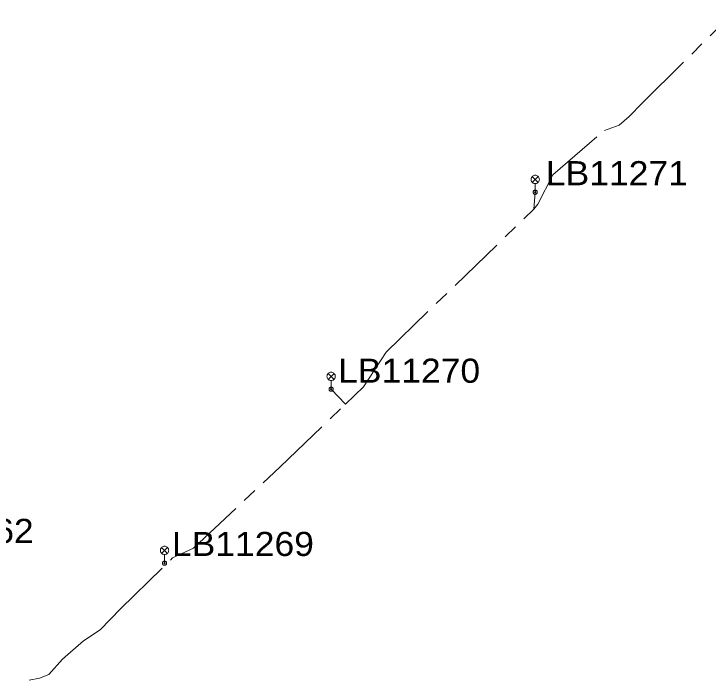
# Model space of a CAD drawing. Extents: x -688049 to -687261, y -973611 to -973038.
# Drawn here: x -687682.8 to -687620.3, y -973588.2 to -973528.3 of the extents above; entities that cross this region are included whole.
import ezdxf

# ---------------------------------------------------------------- set-up
doc = ezdxf.new("R2010")
doc.units = 0
doc.header["$LTSCALE"] = 0.87
doc.linetypes.add('LONG_DASH_SHORT_DASH', pattern=[9.9, 6, -1.2, 1.5, -1.2])
doc.layers.add('1', color=7, linetype='Continuous', lineweight=13)

msp = doc.modelspace()

# ---------------------------------------------------------------- linework, layer by layer
at = {"layer": '1'}
for p, q in [((-687636.154, -973542.962), (-687635.624, -973543.492)), ((-687636.154, -973543.492), (-687635.624, -973542.962)), ((-687635.889, -973544.377), (-687635.889, -973543.602)), ((-687654.505, -973560.675), (-687653.975, -973561.205)), ((-687654.505, -973561.205), (-687653.975, -973560.675)), ((-687654.24, -973562.09), (-687654.24, -973561.315)), ((-687669.484, -973576.322), (-687668.954, -973576.852)), ((-687669.484, -973576.852), (-687668.954, -973576.322)), ((-687669.219, -973577.737), (-687669.219, -973576.962))]:
    msp.add_line(p, q, dxfattribs=at)
at = {"layer": '1', "linetype": 'LONG_DASH_SHORT_DASH'}
msp.add_line((-687652.949, -973563.435), (-687654.24, -973562.09), dxfattribs=at)
msp.add_line((-687652.949, -973563.435), (-687654.24, -973562.09), dxfattribs=at)
msp.add_line((-687652.949, -973563.435), (-687654.24, -973562.09), dxfattribs=at)
msp.add_line((-687652.949, -973563.435), (-687654.24, -973562.09), dxfattribs=at)
msp.add_line((-687652.949, -973563.435), (-687654.24, -973562.09), dxfattribs=at)
for points in [[(-687636.02, -973545.9), (-687635.64, -973545.44), (-687634.29, -973542.81), (-687629.65, -973538.82), (-687628.33, -973538.35), (-687627.45, -973537.56), (-687626.27, -973536.36), (-687618.23, -973528.4), (-687617.66, -973528.34)], [(-687636.02, -973545.9), (-687635.64, -973545.44), (-687634.29, -973542.81), (-687629.65, -973538.82), (-687628.33, -973538.35), (-687627.45, -973537.56), (-687626.27, -973536.36), (-687618.23, -973528.4), (-687617.66, -973528.34)], [(-687636.02, -973545.9), (-687635.64, -973545.44), (-687634.29, -973542.81), (-687629.65, -973538.82), (-687628.33, -973538.35), (-687627.45, -973537.56), (-687626.27, -973536.36), (-687618.23, -973528.4), (-687617.66, -973528.34)], [(-687636.02, -973545.9), (-687635.64, -973545.44), (-687634.29, -973542.81), (-687629.65, -973538.82), (-687628.33, -973538.35), (-687627.45, -973537.56), (-687626.27, -973536.36), (-687618.23, -973528.4), (-687617.66, -973528.34)], [(-687636.02, -973545.9), (-687635.64, -973545.44), (-687634.29, -973542.81), (-687629.65, -973538.82), (-687628.33, -973538.35), (-687627.45, -973537.56), (-687626.27, -973536.36), (-687618.23, -973528.4), (-687617.66, -973528.34)], [(-687636.02, -973545.9), (-687635.64, -973545.44), (-687634.29, -973542.81), (-687629.65, -973538.82), (-687628.33, -973538.35), (-687627.45, -973537.56), (-687626.27, -973536.36), (-687618.23, -973528.4), (-687617.66, -973528.34)], [(-687636.02, -973545.9), (-687635.64, -973545.44), (-687634.29, -973542.81), (-687629.65, -973538.82), (-687628.33, -973538.35), (-687627.45, -973537.56), (-687626.27, -973536.36), (-687618.23, -973528.4), (-687617.66, -973528.34)], [(-687636.02, -973545.9), (-687635.64, -973545.44), (-687634.29, -973542.81), (-687629.65, -973538.82), (-687628.33, -973538.35), (-687627.45, -973537.56), (-687626.27, -973536.36), (-687618.23, -973528.4), (-687617.66, -973528.34)], [(-687652.949, -973563.435), (-687651.34, -973561.89), (-687649.28, -973558.75), (-687636.02, -973545.9), (-687635.88, -973544.37)], [(-687652.949, -973563.435), (-687651.34, -973561.89), (-687649.28, -973558.75), (-687636.02, -973545.9), (-687635.88, -973544.37)], [(-687652.949, -973563.435), (-687651.34, -973561.89), (-687649.28, -973558.75), (-687636.02, -973545.9), (-687635.88, -973544.37)], [(-687652.949, -973563.435), (-687651.34, -973561.89), (-687649.28, -973558.75), (-687636.02, -973545.9), (-687635.88, -973544.37)], [(-687652.949, -973563.435), (-687651.34, -973561.89), (-687649.28, -973558.75), (-687636.02, -973545.9), (-687635.88, -973544.37)], [(-687652.949, -973563.435), (-687651.34, -973561.89), (-687649.28, -973558.75), (-687636.02, -973545.9), (-687635.88, -973544.37)], [(-687652.949, -973563.435), (-687651.34, -973561.89), (-687649.28, -973558.75), (-687636.02, -973545.9), (-687635.88, -973544.37)], [(-687652.949, -973563.435), (-687651.34, -973561.89), (-687649.28, -973558.75), (-687636.02, -973545.9), (-687635.88, -973544.37)], [(-687681.395, -973588.25), (-687680.46, -973588.06), (-687679.62, -973587.76), (-687678.4, -973586.38), (-687676.51, -973584.72), (-687675, -973583.74), (-687673.17, -973581.85), (-687668.49, -973577.26), (-687666.63, -973576.38), (-687658.85, -973569.1), (-687652.949, -973563.435), (-687654.24, -973562.09)], [(-687681.395, -973588.25), (-687680.46, -973588.06), (-687679.62, -973587.76), (-687678.4, -973586.38), (-687676.51, -973584.72), (-687675, -973583.74), (-687673.17, -973581.85), (-687668.49, -973577.26), (-687666.63, -973576.38), (-687658.85, -973569.1), (-687652.949, -973563.435), (-687654.24, -973562.09)], [(-687681.395, -973588.25), (-687680.46, -973588.06), (-687679.62, -973587.76), (-687678.4, -973586.38), (-687676.51, -973584.72), (-687675, -973583.74), (-687673.17, -973581.85), (-687668.49, -973577.26), (-687666.63, -973576.38), (-687658.85, -973569.1), (-687652.949, -973563.435), (-687654.24, -973562.09)], [(-687681.395, -973588.25), (-687680.46, -973588.06), (-687679.62, -973587.76), (-687678.4, -973586.38), (-687676.51, -973584.72), (-687675, -973583.74), (-687673.17, -973581.85), (-687668.49, -973577.26), (-687666.63, -973576.38), (-687658.85, -973569.1), (-687652.949, -973563.435)], [(-687681.395, -973588.25), (-687680.46, -973588.06), (-687679.62, -973587.76), (-687678.4, -973586.38), (-687676.51, -973584.72), (-687675, -973583.74), (-687673.17, -973581.85), (-687668.49, -973577.26), (-687666.63, -973576.38), (-687658.85, -973569.1), (-687652.949, -973563.435)], [(-687681.395, -973588.25), (-687680.46, -973588.06), (-687679.62, -973587.76), (-687678.4, -973586.38), (-687676.51, -973584.72), (-687675, -973583.74), (-687673.17, -973581.85), (-687668.49, -973577.26), (-687666.63, -973576.38), (-687658.85, -973569.1), (-687652.949, -973563.435)], [(-687681.395, -973588.25), (-687680.46, -973588.06), (-687679.62, -973587.76), (-687678.4, -973586.38), (-687676.51, -973584.72), (-687675, -973583.74), (-687673.17, -973581.85), (-687668.49, -973577.26), (-687666.63, -973576.38), (-687658.85, -973569.1), (-687652.949, -973563.435)], [(-687681.395, -973588.25), (-687680.46, -973588.06), (-687679.62, -973587.76), (-687678.4, -973586.38), (-687676.51, -973584.72), (-687675, -973583.74), (-687673.17, -973581.85), (-687668.49, -973577.26), (-687666.63, -973576.38), (-687658.85, -973569.1), (-687652.949, -973563.435)]]:
    msp.add_lwpolyline(points, dxfattribs=at)
at = {"layer": '1'}
for points in [[(-687635.514, -973543.227), (-687635.52, -973543.162), (-687635.537, -973543.099), (-687635.564, -973543.04), (-687635.602, -973542.986), (-687635.648, -973542.94), (-687635.702, -973542.902), (-687635.761, -973542.875), (-687635.824, -973542.858), (-687635.889, -973542.852), (-687635.954, -973542.858), (-687636.017, -973542.875), (-687636.076, -973542.902), (-687636.13, -973542.94), (-687636.176, -973542.986), (-687636.214, -973543.04), (-687636.241, -973543.099), (-687636.258, -973543.162), (-687636.264, -973543.227), (-687636.258, -973543.292), (-687636.241, -973543.355), (-687636.214, -973543.414), (-687636.176, -973543.468), (-687636.13, -973543.514), (-687636.076, -973543.552), (-687636.017, -973543.579), (-687635.954, -973543.596), (-687635.889, -973543.602), (-687635.824, -973543.596), (-687635.761, -973543.579), (-687635.702, -973543.552), (-687635.648, -973543.514), (-687635.602, -973543.468), (-687635.564, -973543.414), (-687635.537, -973543.355), (-687635.52, -973543.292)], [(-687635.699, -973544.377), (-687635.702, -973544.344), (-687635.71, -973544.312), (-687635.724, -973544.282), (-687635.743, -973544.255), (-687635.767, -973544.231), (-687635.794, -973544.212), (-687635.824, -973544.198), (-687635.856, -973544.19), (-687635.889, -973544.187), (-687635.922, -973544.19), (-687635.954, -973544.198), (-687635.984, -973544.212), (-687636.011, -973544.231), (-687636.035, -973544.255), (-687636.054, -973544.282), (-687636.068, -973544.312), (-687636.076, -973544.344), (-687636.079, -973544.377), (-687636.076, -973544.41), (-687636.068, -973544.442), (-687636.054, -973544.472), (-687636.035, -973544.499), (-687636.011, -973544.523), (-687635.984, -973544.542), (-687635.954, -973544.556), (-687635.922, -973544.564), (-687635.889, -973544.567), (-687635.856, -973544.564), (-687635.824, -973544.556), (-687635.794, -973544.542), (-687635.767, -973544.523), (-687635.743, -973544.499), (-687635.724, -973544.472), (-687635.71, -973544.442), (-687635.702, -973544.41)], [(-687635.839, -973544.377), (-687635.84, -973544.368), (-687635.842, -973544.36), (-687635.846, -973544.352), (-687635.851, -973544.345), (-687635.857, -973544.339), (-687635.864, -973544.334), (-687635.872, -973544.33), (-687635.88, -973544.328), (-687635.889, -973544.327), (-687635.898, -973544.328), (-687635.906, -973544.33), (-687635.914, -973544.334), (-687635.921, -973544.339), (-687635.927, -973544.345), (-687635.932, -973544.352), (-687635.936, -973544.36), (-687635.938, -973544.368), (-687635.939, -973544.377), (-687635.938, -973544.386), (-687635.936, -973544.394), (-687635.932, -973544.402), (-687635.927, -973544.409), (-687635.921, -973544.415), (-687635.914, -973544.42), (-687635.906, -973544.424), (-687635.898, -973544.426), (-687635.889, -973544.427), (-687635.88, -973544.426), (-687635.872, -973544.424), (-687635.864, -973544.42), (-687635.857, -973544.415), (-687635.851, -973544.409), (-687635.846, -973544.402), (-687635.842, -973544.394), (-687635.84, -973544.386)], [(-687653.865, -973560.94), (-687653.871, -973560.875), (-687653.888, -973560.812), (-687653.915, -973560.753), (-687653.953, -973560.699), (-687653.999, -973560.653), (-687654.052, -973560.615), (-687654.112, -973560.588), (-687654.175, -973560.571), (-687654.24, -973560.565), (-687654.305, -973560.571), (-687654.368, -973560.588), (-687654.428, -973560.615), (-687654.481, -973560.653), (-687654.527, -973560.699), (-687654.565, -973560.753), (-687654.592, -973560.812), (-687654.609, -973560.875), (-687654.615, -973560.94), (-687654.609, -973561.005), (-687654.592, -973561.068), (-687654.565, -973561.128), (-687654.527, -973561.181), (-687654.481, -973561.227), (-687654.428, -973561.265), (-687654.368, -973561.292), (-687654.305, -973561.309), (-687654.24, -973561.315), (-687654.175, -973561.309), (-687654.112, -973561.292), (-687654.052, -973561.265), (-687653.999, -973561.227), (-687653.953, -973561.181), (-687653.915, -973561.128), (-687653.888, -973561.068), (-687653.871, -973561.005)], [(-687654.05, -973562.09), (-687654.053, -973562.057), (-687654.061, -973562.025), (-687654.075, -973561.995), (-687654.094, -973561.968), (-687654.118, -973561.944), (-687654.145, -973561.925), (-687654.175, -973561.911), (-687654.207, -973561.903), (-687654.24, -973561.9), (-687654.273, -973561.903), (-687654.305, -973561.911), (-687654.335, -973561.925), (-687654.362, -973561.944), (-687654.386, -973561.968), (-687654.405, -973561.995), (-687654.419, -973562.025), (-687654.427, -973562.057), (-687654.43, -973562.09), (-687654.427, -973562.123), (-687654.419, -973562.155), (-687654.405, -973562.185), (-687654.386, -973562.212), (-687654.362, -973562.236), (-687654.335, -973562.255), (-687654.305, -973562.269), (-687654.273, -973562.277), (-687654.24, -973562.28), (-687654.207, -973562.277), (-687654.175, -973562.269), (-687654.145, -973562.255), (-687654.118, -973562.236), (-687654.094, -973562.212), (-687654.075, -973562.185), (-687654.061, -973562.155), (-687654.053, -973562.123)], [(-687654.19, -973562.09), (-687654.191, -973562.081), (-687654.193, -973562.073), (-687654.197, -973562.065), (-687654.202, -973562.058), (-687654.208, -973562.052), (-687654.215, -973562.047), (-687654.223, -973562.043), (-687654.231, -973562.041), (-687654.24, -973562.04), (-687654.249, -973562.041), (-687654.257, -973562.043), (-687654.265, -973562.047), (-687654.272, -973562.052), (-687654.278, -973562.058), (-687654.283, -973562.065), (-687654.287, -973562.073), (-687654.289, -973562.081), (-687654.29, -973562.09), (-687654.289, -973562.099), (-687654.287, -973562.107), (-687654.283, -973562.115), (-687654.278, -973562.122), (-687654.272, -973562.128), (-687654.265, -973562.133), (-687654.257, -973562.137), (-687654.249, -973562.139), (-687654.24, -973562.14), (-687654.231, -973562.139), (-687654.223, -973562.137), (-687654.215, -973562.133), (-687654.208, -973562.128), (-687654.202, -973562.122), (-687654.197, -973562.115), (-687654.193, -973562.107), (-687654.191, -973562.099)], [(-687668.844, -973576.587), (-687668.85, -973576.522), (-687668.867, -973576.459), (-687668.894, -973576.4), (-687668.932, -973576.346), (-687668.978, -973576.3), (-687669.032, -973576.262), (-687669.091, -973576.235), (-687669.154, -973576.218), (-687669.219, -973576.212), (-687669.284, -973576.218), (-687669.347, -973576.235), (-687669.406, -973576.262), (-687669.46, -973576.3), (-687669.506, -973576.346), (-687669.544, -973576.4), (-687669.571, -973576.459), (-687669.588, -973576.522), (-687669.594, -973576.587), (-687669.588, -973576.652), (-687669.571, -973576.715), (-687669.544, -973576.774), (-687669.506, -973576.828), (-687669.46, -973576.874), (-687669.406, -973576.912), (-687669.347, -973576.939), (-687669.284, -973576.956), (-687669.219, -973576.962), (-687669.154, -973576.956), (-687669.091, -973576.939), (-687669.032, -973576.912), (-687668.978, -973576.874), (-687668.932, -973576.828), (-687668.894, -973576.774), (-687668.867, -973576.715), (-687668.85, -973576.652)], [(-687669.029, -973577.737), (-687669.032, -973577.704), (-687669.04, -973577.672), (-687669.054, -973577.642), (-687669.073, -973577.615), (-687669.097, -973577.591), (-687669.124, -973577.572), (-687669.154, -973577.558), (-687669.186, -973577.55), (-687669.219, -973577.547), (-687669.252, -973577.55), (-687669.284, -973577.558), (-687669.314, -973577.572), (-687669.341, -973577.591), (-687669.365, -973577.615), (-687669.384, -973577.642), (-687669.398, -973577.672), (-687669.406, -973577.704), (-687669.409, -973577.737), (-687669.406, -973577.77), (-687669.398, -973577.802), (-687669.384, -973577.832), (-687669.365, -973577.859), (-687669.341, -973577.883), (-687669.314, -973577.902), (-687669.284, -973577.916), (-687669.252, -973577.924), (-687669.219, -973577.927), (-687669.186, -973577.924), (-687669.154, -973577.916), (-687669.124, -973577.902), (-687669.097, -973577.883), (-687669.073, -973577.859), (-687669.054, -973577.832), (-687669.04, -973577.802), (-687669.032, -973577.77)], [(-687669.169, -973577.737), (-687669.17, -973577.728), (-687669.172, -973577.72), (-687669.176, -973577.712), (-687669.181, -973577.705), (-687669.187, -973577.699), (-687669.194, -973577.694), (-687669.202, -973577.69), (-687669.21, -973577.688), (-687669.219, -973577.687), (-687669.228, -973577.688), (-687669.236, -973577.69), (-687669.244, -973577.694), (-687669.251, -973577.699), (-687669.257, -973577.705), (-687669.262, -973577.712), (-687669.266, -973577.72), (-687669.268, -973577.728), (-687669.269, -973577.737), (-687669.268, -973577.746), (-687669.266, -973577.754), (-687669.262, -973577.762), (-687669.257, -973577.769), (-687669.251, -973577.775), (-687669.244, -973577.78), (-687669.236, -973577.784), (-687669.228, -973577.786), (-687669.219, -973577.787), (-687669.21, -973577.786), (-687669.202, -973577.784), (-687669.194, -973577.78), (-687669.187, -973577.775), (-687669.181, -973577.769), (-687669.176, -973577.762), (-687669.172, -973577.754), (-687669.17, -973577.746)]]:
    msp.add_lwpolyline(points, close=True, dxfattribs=at)

# ---------------------------------------------------------------- texts
at = {"layer": '1', "width": 1.1}
for s, p in [('LB11271', (-687634.93, -973543.75)), ('LB11270', (-687653.609, -973561.51)), ('LB11262', (-687693.756, -973575.917)), ('LB11269', (-687668.555, -973577.089))]:
    msp.add_text(s, height=2.168, dxfattribs=at).set_placement(p)

doc.saveas('drawing.dxf')
